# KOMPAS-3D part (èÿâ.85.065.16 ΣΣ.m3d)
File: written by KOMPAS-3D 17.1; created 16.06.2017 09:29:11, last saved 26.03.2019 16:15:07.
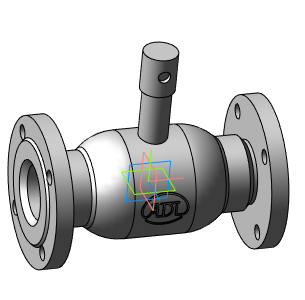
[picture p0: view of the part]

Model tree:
1. Операция без истории:2  (labels: Сталь 20  ГОСТ 1050-88)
